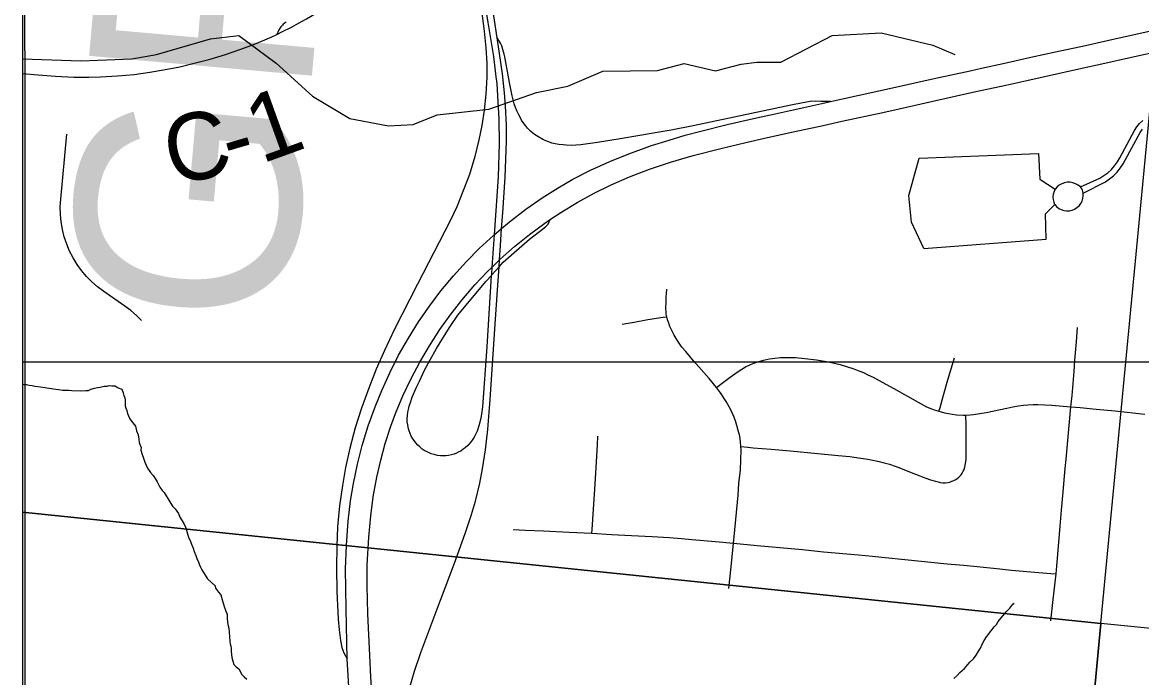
# Model space of a CAD drawing. Extents: x -1.4 to 35.4, y 0 to 22.
# Drawn here: x 24.49 to 25.437, y 13.799 to 14.354 of the extents above; entities that cross this region are included whole.
import ezdxf

# ---------------------------------------------------------------- set-up
doc = ezdxf.new("R2010")
doc.units = 0
for name, color, linetype in [('GM_X_City_Street', 7, 'Continuous'), ('GM_X_County_Road', 7, 'Continuous'), ('GM_X_County_Road_Text', 7, 'Continuous'), ('GM_X_County_Text', 7, 'Continuous'), ('GM_X_Interchange_Ramps', 7, 'Continuous'), ('GM_X_Interstate_Route', 7, 'Continuous'), ('GM_X_Minor_River', 7, 'Continuous'), ('GM_X_Section', 7, 'Continuous'), ('SC_Scratch1', 7, 'Continuous'), ('SH_Border', 7, 'Continuous'), ('SH_Cut_Line', 7, 'Continuous')]:
    doc.layers.add(name, color=color, linetype=linetype)

msp = doc.modelspace()

# ---------------------------------------------------------------- linework, layer by layer
at = {"layer": 'GM_X_City_Street'}
for p, q in [((25.24886, 14.23871), (25.34992, 14.24284)), ((25.25287, 14.16219), (25.35649, 14.17012))]:
    msp.add_line(p, q, dxfattribs=at)
for points in [[(25.38542, 14.21448), (25.40193, 14.22195), (25.40542, 14.22404), (25.40867, 14.22647), (25.41166, 14.22922), (25.41436, 14.23225), (25.41675, 14.23554), (25.41878, 14.23906), (25.43126, 14.26207), (25.43321, 14.26524), (25.43555, 14.26814), (25.43823, 14.27072)], [(25.38777, 14.20925), (25.40662, 14.2187), (25.41015, 14.22116), (25.41343, 14.22392), (25.41645, 14.22698), (25.41916, 14.23031), (25.42155, 14.23388), (25.4236, 14.23765), (25.43612, 14.26063), (25.43806, 14.26335)], [(24.59065, 14.1012), (24.5862, 14.10567), (24.58144, 14.10981), (24.57639, 14.11358), (24.55853, 14.12591), (24.55336, 14.12978), (24.5485, 14.13403), (24.54397, 14.13863), (24.53981, 14.14356), (24.53602, 14.1488), (24.53265, 14.1543), (24.5297, 14.16004), (24.5272, 14.166), (24.52515, 14.17212), (24.52358, 14.17838), (24.52248, 14.18474), (24.52187, 14.19117), (24.52174, 14.19762), (24.5221, 14.20407), (24.5273, 14.25902)], [(25.34992, 14.24284), (25.35119, 14.22111), (25.36415, 14.21258)], [(25.25287, 14.16219), (25.24238, 14.18471), (25.24009, 14.20722), (25.24886, 14.23871)], [(25.36371, 14.19946), (25.36528, 14.19772), (25.36714, 14.19629), (25.3692, 14.1952), (25.37144, 14.19447), (25.37376, 14.19416), (25.3761, 14.19424), (25.37839, 14.19474), (25.38056, 14.19562), (25.38254, 14.19687), (25.38428, 14.19844), (25.38572, 14.20029), (25.38681, 14.20236), (25.38754, 14.20459), (25.38785, 14.20691), (25.38777, 14.20925), (25.38762, 14.21041), (25.38729, 14.21154), (25.38681, 14.21261), (25.38619, 14.21359), (25.38542, 14.21448)], [(25.38542, 14.21448), (25.38354, 14.216), (25.38143, 14.21717), (25.37915, 14.21797), (25.37677, 14.21838), (25.37435, 14.21837), (25.37197, 14.21795), (25.3697, 14.21713), (25.3676, 14.21594), (25.36573, 14.21441), (25.36415, 14.21258)], [(25.36415, 14.21258), (25.36313, 14.21054), (25.36248, 14.20835), (25.3622, 14.20608), (25.36233, 14.20379), (25.36283, 14.20157), (25.36362, 14.19968)], [(25.35649, 14.17012), (25.35598, 14.19175), (25.36371, 14.19946)], [(25.08788, 13.87433), (25.08974, 13.89276), (25.09174, 13.91272), (25.09229, 13.91814), (25.09563, 13.95336), (25.09638, 13.96328), (25.09755, 13.97503), (25.09811, 13.99181), (25.09796, 13.99459), (25.09774, 13.99863), (25.09698, 14.00353), (25.09583, 14.00829), (25.09453, 14.01254), (25.09343, 14.01626), (25.09192, 14.02019), (25.09072, 14.02304), (25.08918, 14.02639), (25.08554, 14.03287), (25.08076, 14.04014), (25.0774, 14.04462), (25.07104, 14.05222), (25.058, 14.06719), (25.05525, 14.07032), (25.05126, 14.07497), (25.04813, 14.07876), (25.04456, 14.08371), (25.04138, 14.08892), (25.03911, 14.09333), (25.03781, 14.09639), (25.03687, 14.09917), (25.03591, 14.10202), (25.03524, 14.10456), (25.03486, 14.10662), (25.03465, 14.10908), (25.03454, 14.11114), (25.03464, 14.11734), (25.03485, 14.12171), (25.03504, 14.12383), (25.0354, 14.12786)], [(24.99761, 14.09829), (25.00765, 14.10006), (25.01929, 14.10206), (25.03214, 14.10408), (25.03524, 14.10456)], [(25.36042, 13.84708), (25.36246, 13.86502), (25.36484, 13.8869), (25.36521, 13.89026), (25.36636, 13.90333), (25.36845, 13.92718), (25.36938, 13.94077), (25.37045, 13.95314), (25.37257, 13.97599), (25.37336, 13.984), (25.37748, 14.02829), (25.3784, 14.03774), (25.37904, 14.04449), (25.38012, 14.05821), (25.38087, 14.06764), (25.38212, 14.08333), (25.38307, 14.09533)], [(25.0774, 14.04462), (25.08215, 14.04827), (25.08879, 14.05336), (25.09489, 14.05757), (25.09874, 14.06005), (25.10202, 14.06209), (25.10623, 14.06412), (25.10884, 14.06521), (25.11248, 14.06645), (25.1172, 14.06775), (25.12229, 14.06885), (25.12673, 14.06957), (25.13152, 14.07001), (25.13479, 14.07015), (25.13835, 14.07008), (25.14411, 14.06991), (25.1521, 14.06923), (25.16195, 14.06807), (25.1723, 14.06634), (25.18191, 14.0641), (25.19369, 14.06043), (25.19796, 14.05881), (25.2017, 14.05723), (25.20559, 14.0554), (25.21005, 14.05327), (25.2177, 14.04919), (25.2274, 14.04369), (25.24797, 14.03207), (25.25523, 14.02838), (25.2588, 14.02683), (25.26161, 14.02576), (25.26567, 14.02451), (25.26763, 14.0239), (25.2705, 14.02319), (25.27377, 14.02247), (25.27675, 14.02203), (25.2806, 14.0216), (25.28605, 14.02124), (25.28844, 14.02128), (25.29216, 14.02145), (25.29506, 14.02177), (25.30555, 14.02346), (25.3232, 14.02724), (25.32836, 14.02836), (25.33291, 14.02907), (25.33723, 14.02959), (25.34086, 14.02992), (25.34537, 14.03017), (25.34948, 14.03019), (25.3612, 14.02959), (25.37748, 14.02829), (25.38532, 14.02766), (25.39878, 14.02641), (25.41478, 14.02472), (25.44013, 14.02212)], [(25.26567, 14.02451), (25.26659, 14.0277), (25.26961, 14.03821), (25.27333, 14.05119), (25.27872, 14.06963)], [(25.09796, 13.99459), (25.10401, 13.99405), (25.10832, 13.99367), (25.12374, 13.99236), (25.13961, 13.99091), (25.16316, 13.98869), (25.18041, 13.98705), (25.19026, 13.98609), (25.19948, 13.98486), (25.20539, 13.984), (25.21108, 13.98284), (25.21519, 13.98198), (25.2193, 13.9809), (25.22369, 13.9796), (25.2286, 13.97801), (25.23314, 13.97634), (25.23946, 13.97387), (25.24587, 13.97128), (25.25458, 13.96787), (25.25855, 13.96654), (25.26273, 13.9652), (25.26488, 13.96463), (25.26674, 13.96423), (25.26885, 13.96398), (25.27125, 13.96389), (25.27322, 13.96419), (25.27491, 13.9646), (25.27671, 13.9652), (25.2784, 13.96588), (25.27987, 13.9667), (25.28106, 13.96744), (25.28246, 13.96856), (25.28341, 13.96946), (25.28449, 13.97075), (25.28527, 13.97195), (25.28631, 13.97383), (25.28691, 13.97528), (25.28757, 13.97719), (25.28799, 13.97885), (25.28846, 13.98173), (25.28864, 13.98377), (25.28881, 13.99433), (25.28885, 13.99805), (25.28859, 14.01233), (25.28844, 14.02128)], [(24.97185, 13.92119), (24.97203, 13.9244), (24.97307, 13.94171), (24.97414, 13.95435), (24.97513, 13.97214), (24.97647, 13.99595), (24.97688, 14.00332)], [(24.90508, 13.92436), (24.91531, 13.92387), (24.93081, 13.92314), (24.95264, 13.9221), (24.97185, 13.92119), (24.98845, 13.92026), (25.00526, 13.91933), (25.02288, 13.91838), (25.03733, 13.9176), (25.04763, 13.91681), (25.05656, 13.916), (25.07642, 13.91419), (25.09174, 13.91272), (25.11189, 13.91078), (25.13103, 13.90918), (25.1501, 13.9074), (25.16798, 13.90562), (25.19764, 13.90286), (25.20949, 13.9017), (25.21736, 13.90093), (25.23956, 13.89873), (25.26978, 13.89573), (25.27599, 13.89514), (25.28678, 13.89407), (25.31456, 13.8914), (25.32709, 13.89007), (25.34337, 13.88864), (25.36042, 13.88726), (25.36484, 13.8869)]]:
    msp.add_lwpolyline(points, dxfattribs=at)
at = {"layer": 'GM_X_County_Road'}
for points in [[(24.48967, 14.89831), (24.48967, 13.93893), (25.40277, 13.84491), (25.49799, 14.83922), (24.49302, 14.93411)], [(24.48967, 13.93893), (24.48967, 13.05458), (25.32857, 13.05458), (25.40277, 13.84491)], [(25.32857, 13.05458), (26.32634, 13.05458), (26.39247, 13.74598), (25.40277, 13.84491)]]:
    msp.add_lwpolyline(points, close=True, dxfattribs=at)
for points in [[(24.7051, 14.3436), (24.70996, 14.34589), (24.71692, 14.34934), (24.72411, 14.35333), (24.73018, 14.35678), (24.75327, 14.37015), (24.80543, 14.40088)], [(24.48967, 14.31054), (24.50293, 14.30933), (24.51774, 14.30816), (24.53314, 14.30748), (24.54607, 14.30731), (24.55591, 14.30755), (24.57006, 14.30838), (24.58418, 14.30968), (24.59761, 14.31145), (24.60913, 14.31342), (24.62303, 14.31623), (24.63744, 14.31962), (24.64873, 14.3227), (24.66169, 14.32667), (24.67453, 14.33108), (24.6861, 14.33535), (24.70029, 14.34133), (24.7051, 14.3436)]]:
    msp.add_lwpolyline(points, dxfattribs=at)
at = {"layer": 'GM_X_County_Text'}
msp.add_lwpolyline([(24.48967, 15.27515), (24.48967, 14.06648), (28.48645, 14.06648)], dxfattribs=at)
at = {"layer": 'GM_X_Interchange_Ramps'}
for points in [[(24.89168, 14.34076), (24.88934, 14.3557), (24.88647, 14.37347), (24.88336, 14.39308), (24.88127, 14.40658), (24.87932, 14.41947), (24.87627, 14.4386), (24.87559, 14.44279), (24.87163, 14.46665)], [(24.87536, 14.40465), (24.87462, 14.40124), (24.87418, 14.39922), (24.87409, 14.39666), (24.87427, 14.39313), (24.87781, 14.36795), (24.88072, 14.3464), (24.88219, 14.33216), (24.88285, 14.3191), (24.88282, 14.30726), (24.88208, 14.29296), (24.88073, 14.27932), (24.87878, 14.26639), (24.87626, 14.25418), (24.87269, 14.2403), (24.8681, 14.225)], [(24.87536, 14.40465), (24.8763, 14.39905), (24.88371, 14.35369), (24.88846, 14.32488), (24.89063, 14.30762), (24.89132, 14.30192), (24.89202, 14.29153), (24.89302, 14.27168), (24.89331, 14.25118), (24.89251, 14.22309)], [(24.71299, 14.35395), (24.7106, 14.3522), (24.70982, 14.35142), (24.70849, 14.35009), (24.7078, 14.34904), (24.70664, 14.34685), (24.7051, 14.3436)], [(24.89829, 14.22265), (24.89954, 14.25314), (24.89944, 14.26683), (24.89875, 14.28299), (24.8979, 14.29415), (24.89619, 14.31024), (24.89376, 14.32747), (24.89168, 14.34076)], [(24.93585, 14.25226), (24.93369, 14.25312), (24.93082, 14.25433), (24.92594, 14.25706), (24.92339, 14.25876), (24.92191, 14.25995), (24.91984, 14.26175), (24.91741, 14.26425), (24.91557, 14.26652), (24.91364, 14.26901), (24.91231, 14.27106), (24.91162, 14.27231), (24.90992, 14.27556), (24.90859, 14.27827), (24.9072, 14.28165), (24.90616, 14.28485), (24.90438, 14.29146), (24.90199, 14.30272), (24.898, 14.3245), (24.89755, 14.32673), (24.89704, 14.32883), (24.89656, 14.33066), (24.89556, 14.33377), (24.89457, 14.33604), (24.89376, 14.33755), (24.89168, 14.34076)], [(25.17389, 14.28674), (25.16559, 14.28685), (25.16108, 14.2869), (25.15673, 14.28662), (25.15343, 14.28621), (25.14157, 14.28381), (25.05766, 14.26603), (25.03889, 14.26254), (25.02888, 14.26073), (25.01231, 14.2579), (24.99582, 14.25516), (24.97654, 14.25201), (24.96251, 14.25005), (24.95818, 14.24972), (24.95445, 14.24961), (24.95012, 14.24972), (24.94757, 14.24993), (24.94388, 14.25035), (24.94079, 14.25093), (24.93805, 14.25155), (24.93585, 14.25226)], [(24.8681, 14.225), (24.85754, 14.19743), (24.85185, 14.18566), (24.82421, 14.13217), (24.80486, 14.09396), (24.79631, 14.07605), (24.78934, 14.06015), (24.78292, 14.04402), (24.77681, 14.02711), (24.7715, 14.01059), (24.76686, 13.99323), (24.76332, 13.97688), (24.76062, 13.96162), (24.75825, 13.94444), (24.7566, 13.92654), (24.75581, 13.91045), (24.75554, 13.89185), (24.75592, 13.872), (24.75707, 13.84845), (24.75799, 13.83936), (24.7589, 13.83035), (24.76, 13.82447), (24.76183, 13.81988), (24.76478, 13.81481)], [(24.89251, 14.22309), (24.88906, 14.17389), (24.88713, 14.14625), (24.88672, 14.14042), (24.88666, 14.13952), (24.88461, 14.10697), (24.88278, 14.07912), (24.87929, 14.02835), (24.87842, 14.02192), (24.87793, 14.01889), (24.87704, 14.01525), (24.87623, 14.01217), (24.87475, 14.00771), (24.8733, 14.00474), (24.87208, 14.00243), (24.87053, 14.00002), (24.86888, 13.99767), (24.86684, 13.99538), (24.86465, 13.9935), (24.86296, 13.99227), (24.8608, 13.99084), (24.85925, 13.99001), (24.85726, 13.98894), (24.85531, 13.98824), (24.8529, 13.98761), (24.85046, 13.98714), (24.84829, 13.98689), (24.84614, 13.98679), (24.84357, 13.98679), (24.84118, 13.98707), (24.83819, 13.98781), (24.8358, 13.98856), (24.83357, 13.98945), (24.83183, 13.9903), (24.82978, 13.9914), (24.8281, 13.99254), (24.82608, 13.99428), (24.82444, 13.99588), (24.82285, 13.99766), (24.82127, 13.99971), (24.82019, 14.00125), (24.81896, 14.0034), (24.81798, 14.00571), (24.81714, 14.00798), (24.81665, 14.0095), (24.81627, 14.01097), (24.81593, 14.0131), (24.81557, 14.01556), (24.81547, 14.01704), (24.81542, 14.01835), (24.81563, 14.02099), (24.81609, 14.02386), (24.8165, 14.02606), (24.81715, 14.02869), (24.81814, 14.03191), (24.81967, 14.03635), (24.82337, 14.04495), (24.82578, 14.05), (24.83014, 14.0593), (24.8349, 14.06812), (24.84019, 14.07755), (24.84711, 14.08868), (24.85172, 14.09622), (24.85844, 14.1058), (24.88198, 14.13442), (24.88616, 14.13897)], [(24.8177, 13.7908), (24.82177, 13.80447), (24.82712, 13.82034), (24.83969, 13.8541), (24.85546, 13.89599), (24.86463, 13.92113), (24.86988, 13.9371), (24.87318, 13.94847), (24.87684, 13.96361), (24.87922, 13.97585), (24.88167, 13.99183), (24.88369, 14.00913), (24.88577, 14.03454), (24.89005, 14.09835), (24.89227, 14.13122), (24.89327, 14.14672), (24.89365, 14.15261), (24.89443, 14.16471), (24.89542, 14.17928), (24.89632, 14.19261), (24.89829, 14.22265)], [(24.88719, 14.1401), (24.89327, 14.14672), (24.89686, 14.15063), (24.91031, 14.16264), (24.91908, 14.17021), (24.92761, 14.1767), (24.93254, 14.18066), (24.9347, 14.18294), (24.93578, 14.18499), (24.93689, 14.18709)]]:
    msp.add_lwpolyline(points, dxfattribs=at)
at = {"layer": 'GM_X_Interstate_Route'}
for points in [[(24.76694, 13.77696), (24.76478, 13.81481), (24.76367, 13.85734), (24.7633, 13.89113), (24.76405, 13.91086), (24.76558, 13.93131), (24.76761, 13.94859), (24.77, 13.96331), (24.77337, 13.97974), (24.77735, 13.99539), (24.78238, 14.01205), (24.78839, 14.02838), (24.79398, 14.0422), (24.80065, 14.05692), (24.80824, 14.07188), (24.8165, 14.08648), (24.82508, 14.10018), (24.83424, 14.11348), (24.84399, 14.12636), (24.85469, 14.13928), (24.86555, 14.15124), (24.87648, 14.16227), (24.88879, 14.17366), (24.89542, 14.17928), (24.90206, 14.18491), (24.91585, 14.19552), (24.92964, 14.20506), (24.94331, 14.21367), (24.95564, 14.22088), (24.97053, 14.22858), (24.98694, 14.23603), (25.00307, 14.24255), (25.02236, 14.24949), (25.03718, 14.25413), (25.05087, 14.25823), (25.06408, 14.26174), (25.08643, 14.26714), (25.11124, 14.27289), (25.12704, 14.27626), (25.13975, 14.27922), (25.15128, 14.28173), (25.16645, 14.28506), (25.17389, 14.28674), (25.18402, 14.28904), (25.22893, 14.29893), (25.2617, 14.30616), (25.29208, 14.31263), (25.30176, 14.31486), (25.31997, 14.31885), (25.34361, 14.32418), (25.36425, 14.32868), (25.38975, 14.33423), (25.41583, 14.34), (25.45283, 14.34821)], [(24.78719, 13.76001), (24.78478, 13.79971), (24.78375, 13.81771), (24.78204, 13.85312), (24.78149, 13.87679), (24.78162, 13.89424), (24.78289, 13.91791), (24.78458, 13.93593), (24.78678, 13.95201), (24.78977, 13.96861), (24.79311, 13.98322), (24.79694, 13.99708), (24.80176, 14.01194), (24.80564, 14.0225), (24.81192, 14.03748), (24.81885, 14.05216), (24.82612, 14.06598), (24.83433, 14.08), (24.84315, 14.09363), (24.85185, 14.10585), (24.86179, 14.11869), (24.87282, 14.13144), (24.88355, 14.14276), (24.88713, 14.14625), (24.89365, 14.15261), (24.89427, 14.15322), (24.90638, 14.16403), (24.91899, 14.17426), (24.93206, 14.18387), (24.93689, 14.18709), (24.94557, 14.19287), (24.95947, 14.20125), (24.97372, 14.20903), (24.98827, 14.2162), (25.0037, 14.22299), (25.02059, 14.22952), (25.03833, 14.23547), (25.05749, 14.24104), (25.08102, 14.24706), (25.10221, 14.25208), (25.11798, 14.25559), (25.14224, 14.261), (25.16774, 14.26655), (25.18353, 14.27), (25.21812, 14.27753), (25.23206, 14.28063), (25.26295, 14.28769), (25.28055, 14.29159), (25.29694, 14.29517), (25.32245, 14.30068), (25.34004, 14.30458), (25.35642, 14.30807), (25.38673, 14.31483), (25.40613, 14.31918), (25.42615, 14.32363), (25.45707, 14.33053)]]:
    msp.add_lwpolyline(points, dxfattribs=at)
at = {"layer": 'GM_X_Minor_River'}
for points in [[(24.48967, 14.32276), (24.53904, 14.32104), (24.58232, 14.32282), (24.60326, 14.32657), (24.64904, 14.33969), (24.673, 14.34262), (24.7044, 14.31921), (24.73532, 14.29125), (24.76681, 14.2724), (24.79969, 14.26603), (24.82057, 14.26713), (24.84084, 14.27545), (24.88457, 14.28026), (24.92506, 14.29424), (24.95134, 14.29978), (24.98119, 14.31246), (25.02748, 14.31304), (25.04998, 14.31903), (25.07641, 14.3128), (25.09815, 14.31844), (25.11145, 14.32006), (25.13194, 14.32003), (25.17526, 14.34268), (25.21665, 14.34488), (25.26045, 14.3345), (25.27926, 14.32652)], [(24.48967, 14.04743), (24.49112, 14.04716), (24.49302, 14.04713), (24.49529, 14.04672), (24.49794, 14.0463), (24.50021, 14.04588), (24.50286, 14.04546), (24.50513, 14.04504), (24.50854, 14.0446), (24.51044, 14.0442), (24.51233, 14.04416), (24.51801, 14.04331), (24.52066, 14.04289), (24.52369, 14.04246), (24.52673, 14.04241), (24.52901, 14.04238), (24.53166, 14.04195), (24.53849, 14.04184), (24.54343, 14.04214), (24.54571, 14.0421), (24.54762, 14.04321), (24.55067, 14.04392), (24.55334, 14.04464), (24.55562, 14.04498), (24.55905, 14.04569), (24.56133, 14.04565), (24.56324, 14.04638), (24.56551, 14.04596), (24.56816, 14.04592), (24.5708, 14.04435), (24.57382, 14.04317), (24.5749, 14.04011), (24.57563, 14.03782), (24.57636, 14.03591), (24.57671, 14.03401), (24.57667, 14.03173), (24.57663, 14.02907), (24.57736, 14.02716), (24.57809, 14.02525), (24.5788, 14.02258), (24.57953, 14.02067), (24.58063, 14.01799), (24.58212, 14.01607), (24.58547, 14.01184), (24.58617, 14.00803), (24.58763, 14.00459), (24.58833, 14.00078), (24.58867, 13.99812), (24.58939, 13.99583), (24.59012, 13.99391), (24.59008, 13.99164), (24.59116, 13.98782), (24.59225, 13.98477), (24.59333, 13.98133), (24.59553, 13.97636), (24.59813, 13.97252), (24.60037, 13.9702), (24.60223, 13.96752), (24.6037, 13.96484), (24.60481, 13.96254), (24.60591, 13.96024), (24.60814, 13.95755), (24.60963, 13.95562), (24.61444, 13.94795), (24.61666, 13.94412), (24.6189, 13.9418), (24.62039, 13.93988), (24.62188, 13.93796), (24.62297, 13.9349), (24.62482, 13.93183), (24.6263, 13.92953), (24.62777, 13.92647), (24.62849, 13.9238), (24.62958, 13.92074), (24.62993, 13.91884), (24.63066, 13.91693), (24.63177, 13.91501)], [(24.63177, 13.91501), (24.63286, 13.91196), (24.63432, 13.90852), (24.63504, 13.90584), (24.6365, 13.9024), (24.63759, 13.89897), (24.63869, 13.89705), (24.63942, 13.89514), (24.64052, 13.89246), (24.64162, 13.89017), (24.6431, 13.88787), (24.64644, 13.88249), (24.6528, 13.8767), (24.65315, 13.87479), (24.65575, 13.87133), (24.65761, 13.86902), (24.65905, 13.86406), (24.66049, 13.8591), (24.66195, 13.85528), (24.66305, 13.85261), (24.66299, 13.84919), (24.66332, 13.84577), (24.66403, 13.84271), (24.66438, 13.84081), (24.6647, 13.83739), (24.66502, 13.83359), (24.66534, 13.82978), (24.66569, 13.8275), (24.66603, 13.82559), (24.66638, 13.82369), (24.66634, 13.82103), (24.66702, 13.81608), (24.66773, 13.81304), (24.66883, 13.80998), (24.67069, 13.80805), (24.67295, 13.80649), (24.67552, 13.80152), (24.67739, 13.79959), (24.67964, 13.79765)], [(25.27831, 13.79818), (25.28101, 13.8008), (25.28333, 13.80342), (25.28525, 13.80491), (25.28718, 13.80677), (25.29027, 13.81014), (25.2922, 13.81239), (25.2949, 13.815), (25.29723, 13.818), (25.29918, 13.82139), (25.30074, 13.82402), (25.30231, 13.82741), (25.30388, 13.83043), (25.30582, 13.83343), (25.30737, 13.83531), (25.30931, 13.83793), (25.31086, 13.83981), (25.31241, 13.84206), (25.31434, 13.84393), (25.3159, 13.84656), (25.32132, 13.85293), (25.32249, 13.85481), (25.32557, 13.8578), (25.32828, 13.86117), (25.32943, 13.86191)]]:
    msp.add_lwpolyline(points, dxfattribs=at)
at = {"layer": 'GM_X_Section'}
msp.add_lwpolyline([(26.47381, 14.7481), (26.39247, 13.74598), (25.40277, 13.84491), (25.49799, 14.83922)], close=True, dxfattribs=at)
at = {"layer": 'SC_Scratch1'}
msp.add_lwpolyline([(24.48967, 14.87591), (24.48967, 13.05458), (31.28967, 13.05458)], dxfattribs=at)
at = {"layer": 'SH_Border'}
msp.add_lwpolyline([(24.48967, 19.85458), (24.49214, 13.05458), (31.28967, 13.05458), (31.28967, 19.85458)], close=True, dxfattribs=at)
at = {"layer": 'SH_Cut_Line'}
msp.add_lwpolyline([(24.48967, 14.87591), (24.48967, 13.05458), (31.28967, 13.05458)], dxfattribs=at)

# ---------------------------------------------------------------- texts
at = {"layer": 'GM_X_County_Road_Text'}
for s, rotation, p in [('1', 19.8638, (24.692, 14.23383)), ('C', 11.90123, (24.61619, 14.21542)), ('-', 16.31365, (24.66615, 14.22614))]:
    msp.add_text(s, height=0.05682, rotation=rotation, dxfattribs=at).set_placement(p)
at = {"layer": 'GM_X_County_Text'}
msp.add_text('GREENE COUNTY', height=0.1893939, rotation=84.91554, dxfattribs=at).set_placement((24.71551, 14.09169))

doc.saveas('drawing.dxf')
